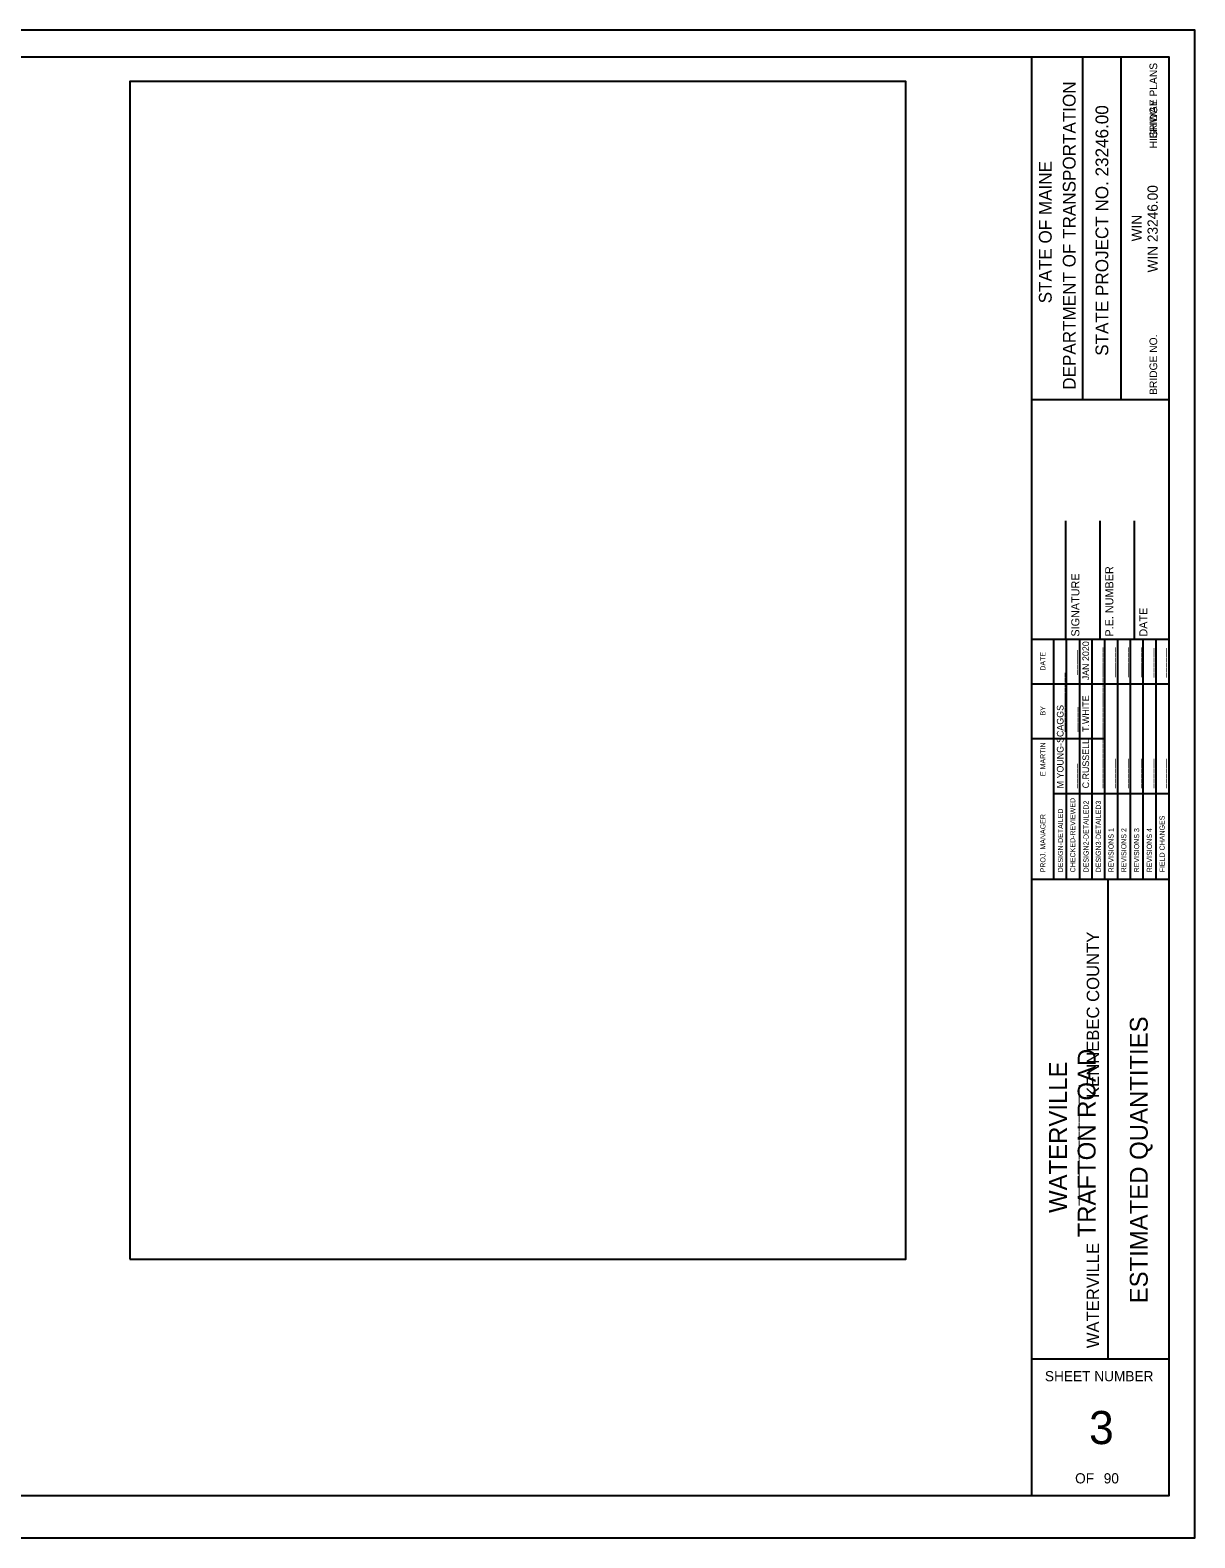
# Model space of a CAD drawing. Extents: x -0.13 to 2.7, y -0.05 to 1.78.
# Drawn here: x 1.282 to 2.698, y -0.051 to 1.782 of the extents above; entities that cross this region are included whole.
import ezdxf

# ---------------------------------------------------------------- set-up
doc = ezdxf.new("R2010")
doc.units = 0
for name, color, linetype in [('BORDER', 7, 'Continuous'), ('BRIDGE_TITLE', 7, 'Continuous'), ('Default', 7, 'Continuous'), ('HIGHWAY_TITLE', 7, 'Continuous'), ('PLOT BOUNDARY', 7, 'Continuous')]:
    doc.layers.add(name, color=color, linetype=linetype)

msp = doc.modelspace()

# ---------------------------------------------------------------- linework, layer by layer
at = {"layer": 'BORDER'}
for p, q in [((2.5, 0), (2.5, 1.75)), ((2.5621, 1.3333), (2.5621, 1.75)), ((2.6087, 1.3333), (2.6087, 1.75)), ((2.5, 1.3332), (2.6667, 1.3332)), ((2.5417, 1.0417), (2.5417, 1.1858)), ((2.5833, 1.0417), (2.5833, 1.1858)), ((2.625, 1.0417), (2.625, 1.1858)), ((2.5, 1.0417), (2.6667, 1.0417)), ((2.5, 0.75), (2.6667, 0.75)), ((2.5932, 0.1667), (2.5932, 0.75)), ((2.5, 0.1667), (2.6667, 0.1667))]:
    msp.add_line(p, q, dxfattribs=at)
msp.add_lwpolyline([(0, 1.75), (2.6667, 1.75), (2.6667, 0), (0, 0)], close=True, dxfattribs=at)
for points in [[(2.5269, 0.9875), (2.5269, 1.0417)], [(2.5269, 0.7501), (2.5269, 1.0299)], [(2.5425, 0.7501), (2.5425, 1.0417)], [(2.558, 1.0417), (2.558, 0.7501)], [(2.5735, 0.7501), (2.5735, 1.0417)], [(2.589, 0.7501), (2.589, 1.0417)], [(2.6046, 0.7501), (2.6046, 1.0417)], [(2.6201, 0.7501), (2.6201, 1.0417)], [(2.6356, 0.7501), (2.6356, 1.0417)], [(2.6512, 0.7501), (2.6512, 1.0417)], [(2.5, 0.9875), (2.6667, 0.9875)], [(2.5, 0.9209), (2.5269, 0.9209)], [(2.5269, 0.9209), (2.589, 0.9209)], [(2.5269, 0.8542), (2.6667, 0.8542)]]:
    msp.add_lwpolyline(points, dxfattribs=at)
at = {"layer": 'Default'}
msp.add_line((1.25, 1.75), (2.5, 1.75), dxfattribs=at)
msp.add_lwpolyline([(1.403, 0.2877), (2.347, 0.2877), (2.347, 1.72), (1.403, 1.72)], close=True, dxfattribs=at)
at = {"layer": 'PLOT BOUNDARY'}
msp.add_lwpolyline([(-0.1349, -0.051), (2.6984, -0.051), (2.6984, 1.7823), (-0.1349, 1.7823)], close=True, dxfattribs=at)

# ---------------------------------------------------------------- texts
at = {"layer": 'BORDER'}
for s, height, p in [('DEPARTMENT OF TRANSPORTATION', 0.015529, (2.5534, 1.3451)), ('STATE PROJECT NO. 23246.00', 0.015529, (2.5932, 1.3864)), ('STATE OF MAINE', 0.015529, (2.5243, 1.4502)), ('WIN 23246.00', 0.012421, (2.6533, 1.4877)), ('WIN', 0.01242, (2.6339, 1.5255)), ('SIGNATURE', 0.00984, (2.558, 1.0449)), ('P.E. NUMBER', 0.009843, (2.5993, 1.0449)), ('DATE', 0.00984, (2.6407, 1.0449)), ('_____', 0.00808, (2.5536, 0.9985)), ('JAN 2020', 0.00808, (2.5698, 0.9918)), ('______', 0.00808, (2.5847, 0.9955)), ('______', 0.00808, (2.6002, 0.9955)), ('______', 0.00808, (2.6157, 0.9955)), ('______', 0.00808, (2.6313, 0.9955)), ('______', 0.00808, (2.6468, 0.995)), ('______', 0.00808, (2.6623, 0.995)), ('DATE', 0.00619, (2.5167, 1.0035)), ('____________', 0.008076, (2.5387, 0.929)), ('____________', 0.008076, (2.5847, 0.929)), ('T.WHITE', 0.00808, (2.5698, 0.929)), ('BY', 0.00619, (2.5167, 0.949)), ('M YOUNG-SCAGGS', 0.008076, (2.5387, 0.8604)), ('_____', 0.00808, (2.5542, 0.929)), ('C.RUSSELL', 0.00808, (2.5698, 0.8604)), ('____________', 0.008076, (2.5847, 0.8604)), ('E MARTIN', 0.00621, (2.5167, 0.8753)), ('_____', 0.00808, (2.5536, 0.8604)), ('______', 0.00808, (2.6002, 0.8604)), ('______', 0.00808, (2.6157, 0.8604)), ('______', 0.00808, (2.6313, 0.8604)), ('______', 0.00808, (2.6468, 0.8604)), ('______', 0.00808, (2.6623, 0.8604)), ('CHECKED-REVIEWED', 0.006212, (2.553, 0.7582)), ('PROJ. MANAGER', 0.006212, (2.5167, 0.7582)), ('DESIGN-DETAILED', 0.006212, (2.5381, 0.7582)), ('DESIGN2-DETAILED2', 0.006212, (2.5692, 0.7582)), ('DESIGN3-DETAILED3', 0.006212, (2.5841, 0.7582)), ('REVISIONS 1', 0.006212, (2.5996, 0.7582)), ('REVISIONS 2', 0.006212, (2.6151, 0.7582)), ('REVISIONS 3', 0.006212, (2.6307, 0.7582)), ('REVISIONS 4', 0.006212, (2.6462, 0.7582)), ('FIELD CHANGES', 0.006212, (2.6617, 0.7582)), ('ESTIMATED QUANTITIES', 0.021738, (2.6411, 0.2342))]:
    msp.add_text(s, height=height, rotation=90, dxfattribs=at).set_placement(p)
for s, height, p in [('SHEET NUMBER', 0.012421, (2.5161, 0.1394)), ('3', 0.0403, (2.5698, 0.063)), ('OF', 0.01242, (2.5528, 0.0152)), ('90', 0.01242, (2.5876, 0.0152))]:
    msp.add_text(s, height=height, dxfattribs=at).set_placement(p)
at = {"layer": 'BRIDGE_TITLE'}
for s, height, p in [('BRIDGE PLANS', 0.009317, (2.6526, 1.6504)), ('BRIDGE NO.', 0.00932, (2.6526, 1.3388)), ('KENNEBEC COUNTY', 0.015119, (2.582, 0.4839)), ('_____________', 0.015119, (2.5541, 0.3532)), ('WATERVILLE', 0.01512, (2.582, 0.1796))]:
    msp.add_text(s, height=height, rotation=90, dxfattribs=at).set_placement(p)
at = {"layer": 'HIGHWAY_TITLE'}
for s, height, p in [('HIGHWAY PLANS', 0.009317, (2.6526, 1.6386)), ('TRAFTON ROAD', 0.021738, (2.5777, 0.3144)), ('WATERVILLE', 0.02174, (2.5429, 0.3441))]:
    msp.add_text(s, height=height, rotation=90, dxfattribs=at).set_placement(p)

doc.saveas('drawing.dxf')
